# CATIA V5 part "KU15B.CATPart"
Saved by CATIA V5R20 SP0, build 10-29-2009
Part number: KU15B
Definition: UNKNOWN
Nomenclature: KU15B
Source: Unknown
Bounding box of the stored display mesh (mm): x -16 to 16, y -16 to 16, z -12 to 9.5
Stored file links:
  C:\Users\Utente\Desktop\IO LAVORO\3D X SITO CF\X 3D SITO CF 27-09-2020\KU15B\KU15B.CATPart
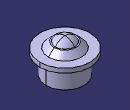
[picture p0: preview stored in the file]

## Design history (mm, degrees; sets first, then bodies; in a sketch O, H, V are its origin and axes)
Body1 "NONE" (main body)
  Solid1: solid without history
Body2 "NONE"
  Solid2: solid without history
